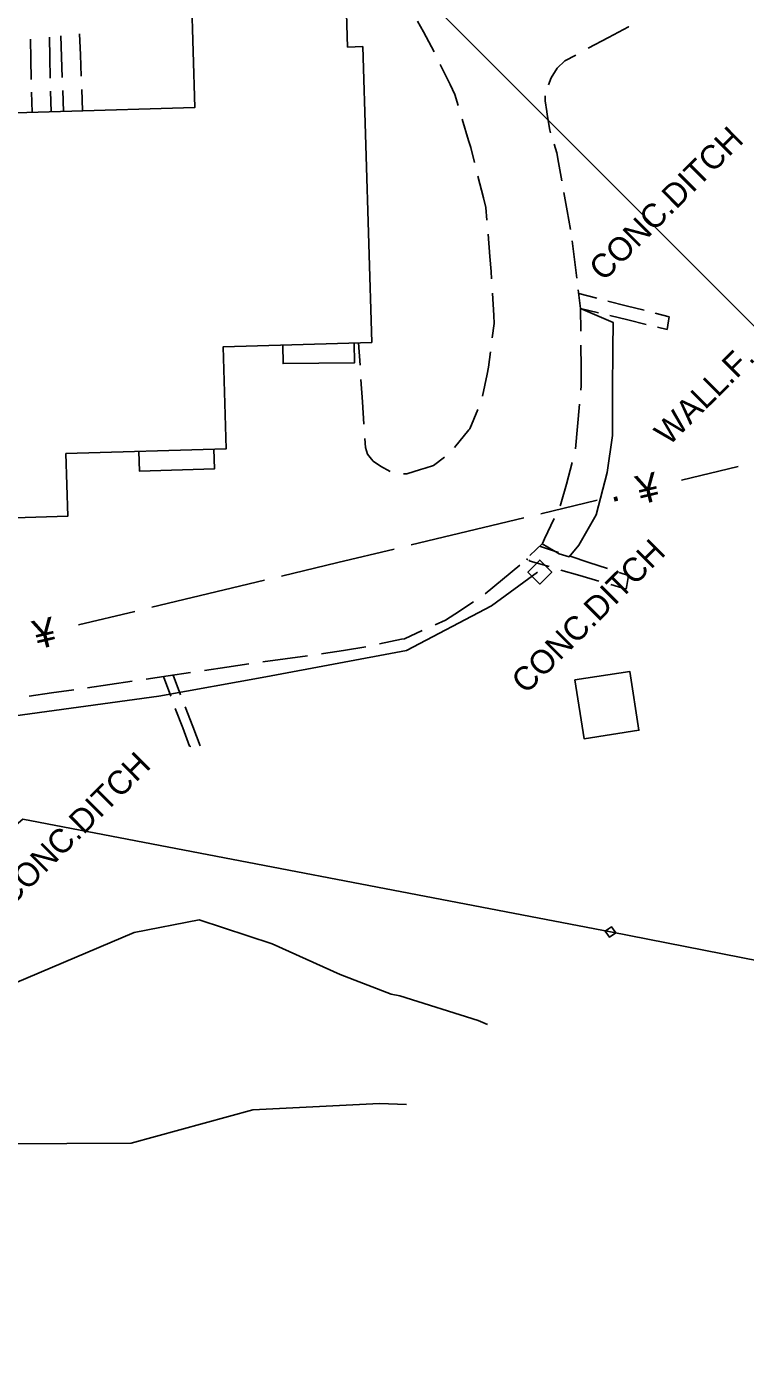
# Model space of a CAD drawing. Extents: x 2443269 to 2494951, y 591171 to 622130.
# Drawn here: x 2463059.1 to 2463183.1, y 604011.5 to 604240.6 of the extents above; entities that cross this region are included whole.
import ezdxf

# ---------------------------------------------------------------- set-up
doc = ezdxf.new("R2010")
doc.units = 0
for name, color, linetype in [('SURVEY - DRAINAGE - Bridges', 7, 'Continuous'), ('SURVEY - DRAINAGE - Natural Features', 7, 'Continuous'), ('SURVEY - DRAINAGE - Pipes and Culverts Text', 7, 'Continuous'), ('SURVEY - NON-TRANSPORTATION - Buildings', 7, 'Continuous'), ('SURVEY - NON-TRANSPORTATION - Features', 7, 'Continuous'), ('SURVEY - NON-TRANSPORTATION - Features Text', 7, 'Continuous'), ('SURVEY - PROPERTY - Property Lines', 7, 'Continuous'), ('SURVEY - TRANSPORTATION - Features', 7, 'Continuous'), ('SURVEY - UTILITIES - Sanitary Sewer with Text', 7, 'Continuous')]:
    doc.layers.add(name, color=color, linetype=linetype)

msp = doc.modelspace()

# ---------------------------------------------------------------- linework, layer by layer
at = {"layer": 'SURVEY - DRAINAGE - Bridges'}
for p, q in [((2463154.299, 604194.56), (2463157.408, 604193.768)), ((2463159.352, 604193.274), (2463162.461, 604192.482)), ((2463157.733, 604191.242), (2463154.614, 604191.994)), ((2463154.614, 604191.994), (2463154.614, 604191.994)), ((2463162.461, 604192.482), (2463165.571, 604191.691)), ((2463167.514, 604191.196), (2463169.922, 604190.583)), ((2463162.801, 604190.019), (2463159.682, 604190.771)), ((2463165.921, 604189.266), (2463162.801, 604190.019)), ((2463169.532, 604188.395), (2463167.87, 604188.796)), ((2463169.795, 604189.871), (2463169.532, 604188.395)), ((2463169.922, 604190.583), (2463169.795, 604189.871)), ((2463150.789, 604149.922), (2463147.553, 604150.987)), ((2463147.553, 604150.987), (2463147.553, 604150.987)), ((2463145.515, 604148.651), (2463145.267, 604148.799)), ((2463145.267, 604148.799), (2463145.267, 604148.799)), ((2463145.92, 604148.412), (2463145.671, 604148.559)), ((2463145.92, 604148.412), (2463149.189, 604147.457)), ((2463156.046, 604148.192), (2463152.811, 604149.257)), ((2463159.282, 604147.127), (2463156.046, 604148.192)), ((2463151.233, 604146.86), (2463154.502, 604145.906)), ((2463154.502, 604145.906), (2463157.772, 604144.951)), ((2463162.865, 604145.948), (2463161.304, 604146.462)), ((2463162.576, 604144.209), (2463162.865, 604145.948)), ((2463159.815, 604144.354), (2463162.471, 604143.579)), ((2463162.471, 604143.579), (2463162.576, 604144.209)), ((2463083.923, 604125.11), (2463082.655, 604128.487)), ((2463082.655, 604128.487), (2463082.655, 604128.487)), ((2463084.348, 604128.736), (2463085.632, 604125.365)), ((2463085.982, 604119.622), (2463084.715, 604122.999)), ((2463086.434, 604123.258), (2463087.717, 604119.887)), ((2463087.717, 604119.887), (2463089.001, 604116.516)), ((2463087.163, 604116.473), (2463085.982, 604119.622)), ((2463087.403, 604116.426), (2463087.163, 604116.473))]:
    msp.add_line(p, q, dxfattribs=at)
at = {"layer": 'SURVEY - DRAINAGE - Natural Features'}
for points in [[(2463138.594, 604068.458), (2463136.976, 604069.163), (2463123.443, 604073.392), (2463121.927, 604073.694), (2463113.134, 604077.109), (2463101.415, 604082.365), (2463088.833, 604086.489), (2463077.603, 604084.33), (2463048.984, 604072.204), (2463030.073, 604062.346), (2463020.142, 604057.136), (2463009.325, 604049.278), (2463000.365, 604037.506), (2462988.945, 604026.142), (2462974.778, 604016.043), (2462958.371, 604000.459), (2462952.432, 603987.136), (2462948.745, 603979.865), (2462939.273, 603973.133), (2462924.08, 603964.373), (2462906.071, 603950.138)], [(2463124.584, 604054.659), (2463119.916, 604054.819), (2463098.065, 604053.727), (2463077.111, 604047.972), (2463054.886, 604047.834), (2463025.73, 604038.464), (2463016.72, 604030.777), (2463006.711, 604018.448), (2462992.869, 604003.123), (2462974.775, 603981.102), (2462964.227, 603971.532), (2462953.856, 603961.106), (2462937.944, 603947.323), (2462924.926, 603937.684), (2462917.518, 603920.39), (2462906.747, 603907.972), (2462892.895, 603891.509), (2462888.975, 603880.538), (2462889.053, 603870.282), (2462898.033, 603858.035), (2462907.492, 603853.678)]]:
    msp.add_lwpolyline(points, dxfattribs=at)
at = {"layer": 'SURVEY - NON-TRANSPORTATION - Buildings'}
msp.add_lwpolyline([(2463012.003, 604234.199), (2463015.05, 604234.291), (2463014.755, 604244.022), (2463041.061, 604244.819), (2463041.651, 604225.301), (2463088.095, 604226.705), (2463087.508, 604246.066), (2463114.125, 604246.869), (2463114.42, 604237.109), (2463117.061, 604237.188), (2463118.607, 604186.148), (2463092.964, 604185.373), (2463093.495, 604167.808), (2463065.844, 604166.971), (2463066.172, 604156.151), (2463042.15, 604155.426), (2463041.829, 604166.085), (2463039.545, 604166.017), (2463039.345, 604172.591), (2463014.378, 604171.837), (2463014.01, 604183.996), (2463013.522, 604183.979)], close=True, dxfattribs=at)
at = {"layer": 'SURVEY - NON-TRANSPORTATION - Features'}
for points in [[(2463147.973, 604151.387), (2463150.949, 604149.639), (2463152.675, 604149.163), (2463154.338, 604151.154), (2463157.317, 604156.414), (2463159.22, 604163.69), (2463160.113, 604170.068), (2463160.106, 604177.916), (2463160.185, 604185.029), (2463160.234, 604189.589), (2463154.614, 604191.994)], [(2463115.592, 604186.056), (2463115.631, 604182.631), (2463103.315, 604182.483), (2463103.275, 604185.685)], [(2463078.413, 604167.352), (2463078.515, 604163.933), (2463091.458, 604164.317), (2463091.356, 604167.742)], [(2463147.219, 604146.515), (2463139.276, 604140.715), (2463124.568, 604132.995), (2463100.306, 604128.418), (2463081.848, 604125.105), (2463054.079, 604121.322), (2463032.488, 604117.949), (2463027.846, 604118.759)]]:
    msp.add_lwpolyline(points, dxfattribs=at)
for points in [[(2463146.561, 604147.546), (2463147.592, 604148.577), (2463149.654, 604146.514), (2463147.592, 604144.452), (2463145.529, 604146.514)], [(2463153.653, 604127.92), (2463163.111, 604129.386), (2463164.689, 604119.225), (2463155.231, 604117.759)]]:
    msp.add_lwpolyline(points, close=True, dxfattribs=at)
at = {"layer": 'SURVEY - PROPERTY - Property Lines'}
msp.add_line((2463087.271, 604286.34), (2463320.503, 604052.889), dxfattribs=at)
msp.add_lwpolyline([(2462730.21, 603640.614), (2462887.351, 603793.774), (2462850.952, 603871.249), (2462902.324, 603971.56), (2462952.239, 604013.863), (2463024.155, 604074.813), (2463036.742, 604085.481), (2463049.33, 604096.149), (2463058.423, 604103.856), (2463159.788, 604084.425), (2463320.503, 604052.889), (2463373.82, 604167.306), (2463394.014, 604256.663), (2463511.955, 604333.69), (2463423.871, 604499.71), (2463541.186, 604663.87)], dxfattribs=at)
msp.add_lwpolyline([(2463159.412, 604084.956), (2463159.943, 604085.331), (2463160.693, 604084.27), (2463159.632, 604083.519), (2463158.881, 604084.581)], close=True, dxfattribs=at)
at = {"layer": 'SURVEY - TRANSPORTATION - Features'}
for p, q in [((2463126.517, 604241.564), (2463127.517, 604239.741)), ((2463065.078, 604235.442), (2463064.938, 604239.032)), ((2463068.349, 604235.745), (2463068.207, 604239.401)), ((2463127.517, 604239.741), (2463128.931, 604237.161)), ((2463159.439, 604238.767), (2463162.901, 604240.623)), ((2463162.901, 604240.623), (2463162.921, 604240.634)), ((2463059.791, 604235.002), (2463059.712, 604238.486)), ((2463063.068, 604235.285), (2463062.987, 604238.839)), ((2463128.931, 604237.161), (2463129.345, 604236.312)), ((2463155.957, 604236.9), (2463159.439, 604238.767)), ((2463059.87, 604231.517), (2463059.791, 604235.002)), ((2463063.148, 604231.73), (2463063.068, 604235.285)), ((2463065.217, 604231.853), (2463065.078, 604235.442)), ((2463068.491, 604232.089), (2463068.349, 604235.745)), ((2463150.598, 604233.457), (2463151.891, 604234.72)), ((2463151.891, 604234.72), (2463153.78, 604235.733)), ((2463130.407, 604234.128), (2463132.108, 604230.633)), ((2463149.578, 604231.827), (2463150.598, 604233.457)), ((2463132.108, 604230.633), (2463132.947, 604228.907)), ((2463149.082, 604230.607), (2463149.578, 604231.827)), ((2463059.998, 604225.856), (2463059.919, 604229.34)), ((2463063.279, 604225.954), (2463063.198, 604229.509)), ((2463065.444, 604226.02), (2463065.305, 604229.609)), ((2463068.722, 604226.148), (2463068.58, 604229.804)), ((2463132.947, 604228.907), (2463133.509, 604227.021)), ((2463148.531, 604227.824), (2463148.539, 604228.688)), ((2463148.784, 604225.997), (2463148.531, 604227.824)), ((2463148.868, 604225.472), (2463148.784, 604225.997)), ((2463149.296, 604222.798), (2463148.868, 604225.472)), ((2463134.202, 604224.693), (2463135.312, 604220.968)), ((2463135.312, 604220.968), (2463135.674, 604219.753)), ((2463149.455, 604222.29), (2463149.296, 604222.798)), ((2463135.674, 604219.753), (2463136.318, 604217.214)), ((2463150.529, 604218.861), (2463150.06, 604220.358)), ((2463150.819, 604217.215), (2463150.529, 604218.861)), ((2463151.381, 604214.025), (2463150.819, 604217.215)), ((2463136.916, 604214.86), (2463137.873, 604211.092)), ((2463152.294, 604208.84), (2463151.732, 604212.03)), ((2463137.873, 604211.092), (2463138.298, 604209.415)), ((2463138.298, 604209.415), (2463138.47, 604207.265)), ((2463152.856, 604205.649), (2463152.294, 604208.84)), ((2463138.663, 604204.844), (2463138.973, 604200.969)), ((2463153.573, 604200.435), (2463153.177, 604203.65)), ((2463138.973, 604200.969), (2463139.181, 604198.366)), ((2463153.97, 604197.219), (2463153.573, 604200.435)), ((2463139.181, 604198.366), (2463139.257, 604197.093)), ((2463139.403, 604194.668), (2463139.636, 604190.788)), ((2463154.614, 604191.994), (2463154.217, 604195.21)), ((2463154.651, 604188.115), (2463154.614, 604191.994)), ((2463154.614, 604191.994), (2463154.614, 604191.994)), ((2463139.719, 604189.419), (2463139.391, 604186.926)), ((2463139.636, 604190.788), (2463139.719, 604189.419)), ((2463116.576, 604182.2), (2463116.323, 604186.079)), ((2463116.323, 604186.079), (2463116.323, 604186.079)), ((2463139.074, 604184.517), (2463138.725, 604181.856)), ((2463154.712, 604181.81), (2463154.674, 604185.69)), ((2463138.725, 604181.856), (2463138.487, 604180.677)), ((2463154.742, 604178.671), (2463154.712, 604181.81)), ((2463116.986, 604175.897), (2463116.734, 604179.776)), ((2463138.487, 604180.677), (2463137.717, 604176.867)), ((2463154.674, 604177.934), (2463154.742, 604178.671)), ((2463117.239, 604172.019), (2463116.986, 604175.897)), ((2463154.101, 604171.655), (2463154.454, 604175.519)), ((2463136.92, 604174.583), (2463135.506, 604171.217)), ((2463135.356, 604171.035), (2463132.886, 604168.034)), ((2463135.506, 604171.217), (2463135.356, 604171.035)), ((2463153.748, 604167.791), (2463154.101, 604171.655)), ((2463117.498, 604168.038), (2463117.396, 604169.595)), ((2463117.852, 604166.85), (2463117.498, 604168.038)), ((2463118.544, 604166.011), (2463117.852, 604166.85)), ((2463118.84, 604165.652), (2463118.544, 604166.011)), ((2463131.153, 604166.355), (2463129.233, 604164.901)), ((2463120.109, 604164.816), (2463118.84, 604165.652)), ((2463121.776, 604163.901), (2463120.109, 604164.816)), ((2463124.657, 604163.49), (2463124.081, 604163.471)), ((2463127.035, 604164.192), (2463124.657, 604163.49)), ((2463127.826, 604164.447), (2463127.035, 604164.192)), ((2463129.233, 604164.901), (2463127.826, 604164.447)), ((2463152.17, 604161.695), (2463153.196, 604165.437)), ((2463151.231, 604158.274), (2463152.17, 604161.695)), ((2463151.091, 604157.973), (2463151.231, 604158.274)), ((2463148.425, 604152.259), (2463150.066, 604155.775)), ((2463148.055, 604151.466), (2463148.425, 604152.259)), ((2463145.883, 604149.39), (2463148.055, 604151.466)), ((2463141.148, 604145.232), (2463144.127, 604147.718)), ((2463138.169, 604142.747), (2463141.148, 604145.232)), ((2463132.908, 604139.277), (2463136.159, 604141.393)), ((2463129.514, 604137.42), (2463131.307, 604138.234)), ((2463131.307, 604138.234), (2463132.908, 604139.277)), ((2463124.246, 604135.026), (2463127.306, 604136.416)), ((2463113.737, 604133.01), (2463117.566, 604133.637)), ((2463119.94, 604134.131), (2463123.739, 604134.92)), ((2463123.739, 604134.92), (2463124.246, 604135.026)), ((2463099.815, 604131.017), (2463103.66, 604131.541)), ((2463103.66, 604131.541), (2463107.504, 604132.065)), ((2463109.907, 604132.392), (2463110.26, 604132.441)), ((2463110.26, 604132.441), (2463113.737, 604133.01)), ((2463083.503, 604128.613), (2463087.341, 604129.18)), ((2463089.739, 604129.535), (2463093.577, 604130.103)), ((2463093.577, 604130.103), (2463097.416, 604130.671)), ((2463069.588, 604126.567), (2463073.427, 604127.128)), ((2463073.427, 604127.128), (2463077.265, 604127.69)), ((2463077.265, 604127.69), (2463077.266, 604127.69)), ((2463079.665, 604128.045), (2463083.503, 604128.613)), ((2463059.511, 604125.092), (2463063.35, 604125.654)), ((2463063.35, 604125.654), (2463067.189, 604126.215))]:
    msp.add_line(p, q, dxfattribs=at)
at = {"layer": 'SURVEY - UTILITIES - Sanitary Sewer with Text'}
for p, q in [((2463172.058, 604162.403), (2463181.781, 604164.739)), ((2463147.749, 604156.563), (2463157.473, 604158.899)), ((2463125.386, 604151.191), (2463144.832, 604155.862)), ((2463112.745, 604148.154), (2463122.469, 604150.49)), ((2463103.022, 604145.818), (2463112.745, 604148.154)), ((2463080.658, 604140.446), (2463100.105, 604145.118)), ((2463068.018, 604137.409), (2463077.741, 604139.745))]:
    msp.add_line(p, q, dxfattribs=at)

# ---------------------------------------------------------------- texts
at = {"layer": 'SURVEY - DRAINAGE - Pipes and Culverts Text'}
for rotation, p in [(44.9, (2463158.602, 604196.537)), (45, (2463145.204, 604125.318)), (44.9, (2463056.345, 604088.621))]:
    msp.add_text('CONC.DITCH', height=4.101, rotation=rotation, dxfattribs=at).set_placement(p)
at = {"layer": 'SURVEY - NON-TRANSPORTATION - Features Text'}
msp.add_text('WALL.F.', height=4.101, rotation=44.8, dxfattribs=at).set_placement((2463169.841, 604168.175))
at = {"layer": 'SURVEY - UTILITIES - Sanitary Sewer with Text'}
for s, p in [('¥', (2463164.944, 604158.123)), ('·', (2463160.082, 604156.955)), ('¥', (2463060.904, 604133.129))]:
    msp.add_text(s, height=5, rotation=13.50818, dxfattribs=at).set_placement(p)

doc.saveas('drawing.dxf')
